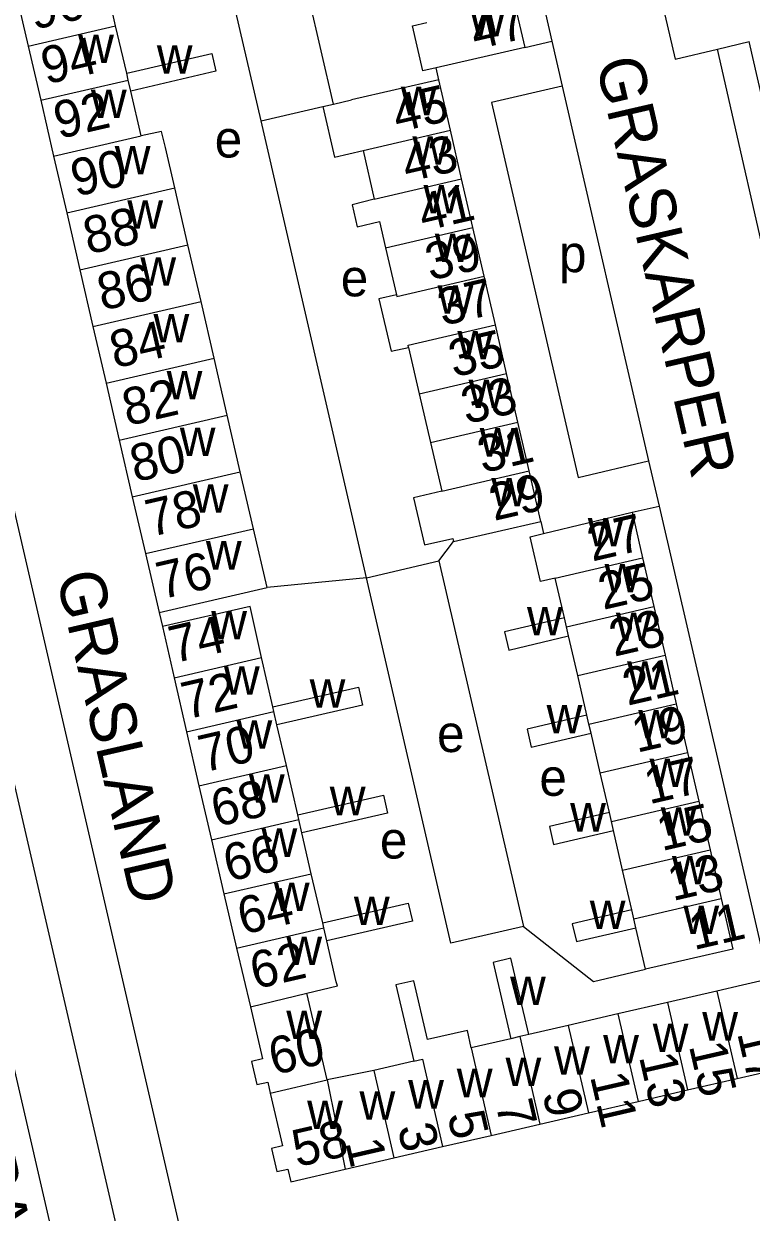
# Model space of a CAD drawing. Extents: x 155696 to 157795, y 382328 to 384028.
# Drawn here: x 156930.4 to 157009.1, y 383217.2 to 383345.7 of the extents above; entities that cross this region are included whole.
import ezdxf

# ---------------------------------------------------------------- set-up
doc = ezdxf.new("R2010")
doc.units = 0
for name, color, linetype in [('BLT_Basislijn', 7, 'Continuous'), ('BLT_Bebouwing', 7, 'Continuous'), ('BLT_Centroide', 7, 'Continuous'), ('BLT_Huisnummer', 7, 'Continuous'), ('BLT_Huisnummer_ tussenligend', 7, 'Continuous'), ('BLT_Onderverdeling_panden', 7, 'Continuous'), ('BLT_Straatnaam', 7, 'Continuous')]:
    doc.layers.add(name, color=color, linetype=linetype)

msp = doc.modelspace()

# ---------------------------------------------------------------- linework, layer by layer
at = {"layer": 'BLT_Basislijn'}
for p, q in [((156976.32, 383392.48), (156987.55, 383343.86)), ((156963.94, 383337.05), (156952.41, 383386.99)), ((156956.1, 383335.24), (156944.56, 383385.17)), ((156999.79, 383346.69), (157000.9, 383341.9)), ((156984.62, 383343.18), (156987.55, 383343.86)), ((156987.55, 383343.86), (156988.67, 383338.99)), ((157005.47, 383342.98), (157008.92, 383343.8)), ((157018.13, 383303.23), (157008.92, 383343.8)), ((157000.9, 383341.9), (157005.47, 383342.98)), ((157014.68, 383302.42), (157005.47, 383342.98)), ((156975.33, 383339.68), (156975.03, 383340.97)), ((156988.67, 383338.99), (156981.02, 383337.22)), ((156988.67, 383338.99), (156998.03, 383298.47)), ((156956.1, 383335.24), (156962.8, 383336.79)), ((156981.02, 383337.22), (156990.4, 383296.67)), ((156967.51, 383285.84), (156956.1, 383335.24)), ((156990.4, 383296.67), (156998.03, 383298.47)), ((156998.03, 383298.47), (156999.16, 383293.59)), ((156996.24, 383292.91), (156999.16, 383293.59)), ((156999.16, 383293.59), (157010.98, 383242.43)), ((156986.36, 383291.93), (156986.67, 383290.61)), ((156975.35, 383287.65), (156976.91, 383289.74)), ((156967.51, 383285.84), (156975.35, 383287.65)), ((156975.35, 383287.65), (156984.48, 383248.13)), ((156967.51, 383285.84), (156956.76, 383284.78)), ((156976.63, 383246.32), (156967.51, 383285.84)), ((156945.07, 383282.06), (156945.44, 383280.56)), ((156984.48, 383248.13), (156976.63, 383246.32))]:
    msp.add_line(p, q, dxfattribs=at)
for points in [[(156983.21, 383030.72), (156967.38, 383099.24), (156870.41, 383519.08), (156869.37, 383522.79), (156868.15, 383526.38), (156866.54, 383529.72), (156865.07, 383532.4), (156812.59, 383620.85)], [(156899.98, 383420.38), (156963.72, 383144.42)], [(156906.38, 383332.24), (156973.29, 383042.58), (156975.17, 383034.43)], [(156984.48, 383248.13), (156992.05, 383242.19), (156997.69, 383243.5)]]:
    msp.add_lwpolyline(points, dxfattribs=at)
at = {"layer": 'BLT_Bebouwing'}
for p, q in [((156940.37, 383345.49), (156939.32, 383350.13)), ((156929.57, 383349.15), (156930.92, 383343.31)), ((156983.5, 383348.06), (156984.62, 383343.18)), ((156972.48, 383345.51), (156974.05, 383345.87)), ((156941.57, 383340.39), (156940.37, 383345.49)), ((156973.6, 383340.64), (156972.48, 383345.51)), ((156930.92, 383343.31), (156932.27, 383337.46)), ((156984.62, 383343.18), (156975.03, 383340.97)), ((156975.03, 383340.97), (156973.6, 383340.64)), ((156975.33, 383339.68), (156965.87, 383337.49)), ((156976.59, 383334.22), (156975.33, 383339.68)), ((156943.12, 383333.6), (156942.02, 383338.45)), ((156932.27, 383337.46), (156933.67, 383331.41)), ((156962.8, 383336.79), (156963.94, 383337.05)), ((156963.94, 383337.05), (156965.87, 383337.49)), ((156977.8, 383328.96), (156976.59, 383334.22)), ((156946.78, 383327.98), (156945.77, 383332.35)), ((156967.14, 383332.03), (156968.35, 383326.77)), ((156933.67, 383331.41), (156935.08, 383325.28)), ((156948.19, 383321.84), (156946.78, 383327.98)), ((156979.02, 383323.69), (156977.8, 383328.96)), ((156935.08, 383325.28), (156936.5, 383319.14)), ((156980.23, 383318.43), (156979.02, 383323.69)), ((156949.61, 383315.7), (156948.19, 383321.84)), ((156969.57, 383321.51), (156970.74, 383316.42)), ((156936.5, 383319.14), (156937.92, 383313)), ((156981.45, 383313.17), (156980.23, 383318.43)), ((156951.03, 383309.56), (156949.61, 383315.7)), ((156937.92, 383313), (156939.34, 383306.86)), ((156982.67, 383307.91), (156981.45, 383313.17)), ((156972.06, 383310.73), (156973.21, 383305.73)), ((156952.44, 383303.42), (156951.03, 383309.56)), ((156983.88, 383302.65), (156982.67, 383307.91)), ((156939.34, 383306.86), (156940.75, 383300.72)), ((156973.21, 383305.73), (156974.43, 383300.47)), ((156953.86, 383297.28), (156952.44, 383303.42)), ((156985.1, 383297.39), (156983.88, 383302.65)), ((156940.75, 383300.72), (156942.17, 383294.58)), ((156974.43, 383300.47), (156975.65, 383295.2)), ((156955.28, 383291.14), (156953.86, 383297.28)), ((156986.36, 383291.93), (156985.1, 383297.39)), ((156942.17, 383294.58), (156943.59, 383288.44)), ((156976.91, 383289.74), (156986.36, 383291.93)), ((156986.67, 383290.61), (156996.24, 383292.91)), ((156996.24, 383292.91), (156997.38, 383287.98)), ((156956.76, 383284.78), (156955.28, 383291.14)), ((156985.23, 383290.27), (156986.67, 383290.61)), ((156986.34, 383285.42), (156985.23, 383290.27)), ((156943.59, 383288.44), (156945.07, 383282.06)), ((156997.38, 383287.98), (156998.59, 383282.71)), ((156987.93, 383285.79), (156986.34, 383285.42)), ((156988.92, 383281.49), (156987.93, 383285.79)), ((156945.07, 383282.06), (156956.76, 383284.78)), ((156954.92, 383282.74), (156945.44, 383280.56)), ((156956.14, 383277.22), (156954.92, 383282.74)), ((156998.59, 383282.71), (156999.81, 383277.45)), ((156945.44, 383280.56), (156946.69, 383275.03)), ((156990.36, 383275.27), (156989.37, 383279.54)), ((156957.38, 383271.87), (156956.14, 383277.22)), ((156999.81, 383277.45), (157001.02, 383272.19)), ((156991.35, 383270.97), (156990.36, 383275.27)), ((156946.69, 383275.03), (156948.04, 383269.19)), ((157001.02, 383272.19), (157002.24, 383266.93)), ((156958.84, 383265.52), (156957.82, 383269.93)), ((156948.04, 383269.19), (156949.39, 383263.34)), ((156992.79, 383264.74), (156991.8, 383269.02)), ((157002.24, 383266.93), (157003.45, 383261.67)), ((156960.07, 383260.19), (156958.84, 383265.52)), ((156993.78, 383260.46), (156992.79, 383264.74)), ((156949.39, 383263.34), (156950.74, 383257.49)), ((157003.45, 383261.67), (157004.67, 383256.41)), ((156995.22, 383254.22), (156994.23, 383258.51)), ((156950.74, 383257.49), (156952.09, 383251.65)), ((156961.54, 383253.83), (156960.52, 383258.26)), ((157004.67, 383256.41), (157005.88, 383251.14)), ((156962.77, 383248.52), (156961.54, 383253.83)), ((156996.21, 383249.94), (156995.22, 383254.22)), ((156952.09, 383251.65), (156953.44, 383245.8)), ((157005.88, 383251.14), (157007.15, 383245.68)), ((156997.69, 383243.5), (156996.66, 383247.99)), ((156953.44, 383245.8), (156954.95, 383239.43)), ((156964.24, 383242.14), (156963.22, 383246.59)), ((157007.15, 383245.68), (156997.69, 383243.5)), ((156961.07, 383240.92), (156964.36, 383241.72)), ((156964.36, 383241.72), (156964.24, 383242.14)), ((157008.2, 383241.79), (157005.42, 383241.15)), ((157010.98, 383242.43), (157008.2, 383241.79)), ((156963.25, 383231.55), (156961.07, 383240.92)), ((157005.42, 383241.15), (157000.06, 383239.91)), ((157000.06, 383239.91), (156994.7, 383238.67)), ((156994.7, 383238.67), (156989.34, 383237.43)), ((156989.34, 383237.43), (156985.07, 383236.45)), ((156983.13, 383236), (156978.82, 383235)), ((156972.62, 383233.57), (156968.29, 383232.57)), ((157007.6, 383231.7), (157013.26, 383233)), ((156968.29, 383232.57), (156963.25, 383231.55)), ((157002.24, 383230.46), (157007.6, 383231.7)), ((156996.88, 383229.22), (157002.24, 383230.46)), ((156991.52, 383227.98), (156996.88, 383229.22)), ((156986.26, 383226.77), (156991.52, 383227.98)), ((156981, 383225.55), (156986.26, 383226.77)), ((156975.74, 383224.34), (156981, 383225.55)), ((156970.48, 383223.12), (156975.74, 383224.34)), ((156965.22, 383221.91), (156970.48, 383223.12)), ((156959.32, 383220.53), (156965.22, 383221.91))]:
    msp.add_line(p, q, dxfattribs=at)
for points in [[(156941.57, 383340.39), (156950.79, 383342.53), (156951.23, 383340.59), (156942.02, 383338.45)], [(156962.8, 383336.79), (156964.05, 383331.3), (156967.14, 383332.03)], [(156945.77, 383332.35), (156945.35, 383334.09), (156943.12, 383333.6)], [(156968.35, 383326.77), (156965.96, 383326.17), (156966.51, 383323.79), (156968.91, 383324.35), (156969.57, 383321.51)], [(156970.74, 383316.42), (156968.86, 383315.98), (156970.18, 383310.32), (156972.06, 383310.73)], [(156975.65, 383295.2), (156972.61, 383294.47), (156973.79, 383289.38), (156976.85, 383290.09), (156976.91, 383289.74)], [(156988.92, 383281.49), (156982.44, 383279.98), (156982.9, 383278.02), (156989.37, 383279.54)], [(156957.38, 383271.87), (156966.63, 383274.01), (156967.08, 383272.06), (156957.82, 383269.93)], [(156991.35, 383270.97), (156984.88, 383269.45), (156985.32, 383267.51), (156991.8, 383269.02)], [(156960.07, 383260.19), (156969.34, 383262.32), (156969.79, 383260.39), (156960.52, 383258.26)], [(156993.78, 383260.46), (156987.31, 383258.95), (156987.75, 383256.99), (156994.23, 383258.51)], [(156962.77, 383248.52), (156972.02, 383250.65), (156972.47, 383248.72), (156963.22, 383246.59)], [(156996.21, 383249.94), (156989.75, 383248.43), (156990.21, 383246.49), (156996.66, 383247.99)], [(156985.07, 383236.45), (156983.14, 383244.7), (156981.21, 383244.25), (156983.13, 383236)], [(156978.82, 383235), (156978.42, 383236.89), (156974.12, 383235.91), (156972.64, 383242.27), (156970.7, 383241.82), (156972.62, 383233.57)], [(156954.95, 383239.43), (156956.25, 383233.82), (156955.07, 383233.55), (156955.65, 383231.04), (156956.83, 383231.29), (156957.1, 383230.12)], [(156957.1, 383230.12), (156958.42, 383224.41), (156957.24, 383224.13), (156957.82, 383221.64), (156959.01, 383221.89), (156959.32, 383220.53)]]:
    msp.add_lwpolyline(points, dxfattribs=at)
at = {"layer": 'BLT_Onderverdeling_panden'}
for p, q in [((156930.92, 383343.31), (156940.37, 383345.49)), ((156932.27, 383337.46), (156941.72, 383339.64)), ((156941.72, 383339.64), (156941.57, 383340.39)), ((156942.02, 383338.45), (156941.72, 383339.64)), ((156967.14, 383332.03), (156976.59, 383334.22)), ((156933.67, 383331.41), (156943.12, 383333.6)), ((156935.08, 383325.28), (156946.78, 383327.98)), ((156968.35, 383326.77), (156977.8, 383328.96)), ((156969.57, 383321.51), (156979.02, 383323.69)), ((156936.5, 383319.14), (156948.19, 383321.84)), ((156937.92, 383313), (156949.61, 383315.7)), ((156939.34, 383306.86), (156951.03, 383309.56)), ((156973.21, 383305.73), (156982.67, 383307.91)), ((156940.75, 383300.72), (156952.44, 383303.42)), ((156974.43, 383300.47), (156983.88, 383302.65)), ((156942.17, 383294.58), (156953.86, 383297.28)), ((156975.65, 383295.2), (156985.1, 383297.39)), ((156943.59, 383288.44), (156955.28, 383291.14)), ((156987.93, 383285.79), (156997.38, 383287.98)), ((156989.14, 383280.53), (156988.92, 383281.49)), ((156989.14, 383280.53), (156998.59, 383282.71)), ((156989.37, 383279.54), (156989.14, 383280.53)), ((156946.69, 383275.03), (156956.14, 383277.22)), ((156990.36, 383275.27), (156999.81, 383277.45)), ((156948.04, 383269.19), (156957.49, 383271.37)), ((156957.49, 383271.37), (156957.38, 383271.87)), ((156957.82, 383269.93), (156957.49, 383271.37)), ((156991.57, 383270.01), (157001.02, 383272.19)), ((156991.57, 383270.01), (156991.35, 383270.97)), ((156991.8, 383269.02), (156991.57, 383270.01)), ((156992.79, 383264.74), (157002.24, 383266.93)), ((156949.39, 383263.34), (156958.84, 383265.52)), ((156994, 383259.48), (157003.45, 383261.67)), ((156950.74, 383257.49), (156960.19, 383259.68)), ((156960.19, 383259.68), (156960.07, 383260.19)), ((156960.52, 383258.26), (156960.19, 383259.68)), ((156994, 383259.48), (156993.78, 383260.46)), ((156994.23, 383258.51), (156994, 383259.48)), ((156995.22, 383254.22), (157004.67, 383256.41)), ((156952.09, 383251.65), (156961.54, 383253.83)), ((156996.43, 383248.96), (157005.88, 383251.14)), ((156996.43, 383248.96), (156996.21, 383249.94)), ((156962.89, 383247.99), (156962.77, 383248.52)), ((156996.66, 383247.99), (156996.43, 383248.96)), ((156953.44, 383245.8), (156962.89, 383247.99)), ((156963.22, 383246.59), (156962.89, 383247.99)), ((156954.95, 383239.43), (156961.07, 383240.92)), ((157005.42, 383241.15), (157007.6, 383231.7)), ((157000.06, 383239.91), (157002.24, 383230.46)), ((156994.7, 383238.67), (156996.88, 383229.22)), ((156989.34, 383237.43), (156991.52, 383227.98)), ((156984.08, 383236.22), (156983.13, 383236)), ((156985.07, 383236.45), (156984.08, 383236.22)), ((156984.08, 383236.22), (156986.26, 383226.77)), ((156978.82, 383235), (156981, 383225.55)), ((156957.1, 383230.12), (156963.25, 383231.55)), ((156963.25, 383231.55), (156965.22, 383221.91)), ((156968.29, 383232.57), (156970.48, 383223.12))]:
    msp.add_line(p, q, dxfattribs=at)
for points in [[(156970.74, 383316.42), (156970.78, 383316.25), (156980.23, 383318.43)], [(156972.06, 383310.73), (156972, 383310.99), (156981.45, 383313.17)], [(156972.62, 383233.57), (156973.56, 383233.79), (156975.74, 383224.34)]]:
    msp.add_lwpolyline(points, dxfattribs=at)

# ---------------------------------------------------------------- texts
at = {"layer": 'BLT_Centroide'}
for s, p in [('w', (156978.7, 383344.38)), ('w', (156936.32, 383341.47)), ('w', (156944.83, 383340.34)), ('w', (156937.7, 383335.53)), ('w', (156971.23, 383335.84)), ('e', (156951.09, 383331.27)), ('w', (156972.47, 383330.5)), ('w', (156940.28, 383329.44)), ('w', (156973.68, 383325.22)), ('w', (156941.64, 383323.56)), ('w', (156974.9, 383319.97)), ('p', (156988.34, 383318.87)), ('w', (156943.05, 383317.41)), ('e', (156964.73, 383316.26)), ('w', (156975.2, 383314.38)), ('w', (156944.47, 383311.28)), ('w', (156977.34, 383309.44)), ('w', (156945.89, 383305.12)), ('w', (156978.55, 383304.19)), ('w', (156947.31, 383299)), ('w', (156979.76, 383298.94)), ('w', (156948.72, 383292.88)), ('w', (156981.01, 383293.56)), ('w', (156991.45, 383289.22)), ('w', (156950.14, 383286.72)), ('w', (156993.26, 383284.25)), ('w', (156950.72, 383279.16)), ('w', (156984.87, 383279.61)), ('w', (156994.48, 383279)), ('w', (156995.7, 383273.72)), ('w', (156952.09, 383273.19)), ('w', (156961.36, 383271.79)), ('w', (156986.99, 383269.01)), ('w', (156996.9, 383268.47)), ('w', (156953.45, 383267.34)), ('e', (156975.14, 383266.99)), ('w', (156998.12, 383263.22)), ('e', (156986.21, 383262.26)), ('w', (156954.79, 383261.5)), ('w', (156963.54, 383260.16)), ('w', (156989.54, 383258.4)), ('w', (156999.34, 383257.94)), ('w', (156956.15, 383255.66)), ('e', (156968.96, 383255.48)), ('w', (157000.55, 383252.69)), ('w', (156957.49, 383249.81)), ('w', (156966.15, 383248.28)), ('w', (156991.66, 383247.86)), ('w', (157001.79, 383247.31)), ('w', (156958.84, 383243.97)), ('w', (156983.04, 383239.65)), ('w', (156958.84, 383235.95)), ('w', (157003.83, 383235.8)), ('w', (156998.47, 383234.56)), ('w', (156993.11, 383233.33)), ('w', (156982.55, 383230.89)), ('w', (156987.8, 383232.11)), ('w', (156977.28, 383229.67)), ('w', (156972.02, 383228.45)), ('w', (156966.75, 383227.23)), ('w', (156961.09, 383226.23))]:
    msp.add_text(s, height=4, dxfattribs=at).set_placement(p)
at = {"layer": 'BLT_Huisnummer'}
for s, rotation, p in [('47', 13.0061, (156979.28, 383342.91)), ('94', 12.986, (156932.85, 383339.16)), ('92', 12.986, (156934.22, 383333.26)), ('45', 13.0061, (156970.86, 383333.97)), ('41', 13.0061, (156973.66, 383323.28)), ('88', 12.986, (156937.41, 383320.78)), ('37', 13.0061, (156975.74, 383313.05)), ('84', 12.986, (156940.27, 383308.46)), ('33', 13.0061, (156978.28, 383302.43)), ('80', 12.986, (156942.46, 383296.15)), ('29', 13.0061, (156981.3, 383291.97)), ('27', 13.0061, (156991.92, 383287.58)), ('76', 12.986, (156945.32, 383283.49)), ('74', 12.986, (156946.67, 383276.58)), ('23', 13.0061, (156994.29, 383277.29)), ('19', 13.0061, (156996.75, 383266.9)), ('70', 12.986, (156949.87, 383264.77)), ('15', 13.0061, (156999.45, 383256.27)), ('66', 12.986, (156952.57, 383252.96)), ('11', 13.0061, (157002.92, 383245.57)), ('62', 12.986, (156955.45, 383241.33)), ('17', 283.0035, (157007.59, 383236.61)), ('13', 283.0035, (156996.97, 383234.06)), ('7', 283.0035, (156981.46, 383228.95)), ('58', 12.986, (156959.99, 383222.1)), ('1', 283.0035, (156965.21, 383224.79))]:
    msp.add_text(s, height=4, rotation=rotation, dxfattribs=at).set_placement(p)
at = {"layer": 'BLT_Huisnummer_ tussenligend'}
for s, rotation, p in [('96', 12.986, (156931.51, 383345.06)), ('43', 13.0061, (156971.88, 383328.58)), ('90', 12.986, (156936.06, 383327.02)), ('39', 13.0061, (156974.4, 383317.95)), ('86', 12.986, (156938.92, 383314.7)), ('35', 13.0061, (156976.93, 383307.49)), ('82', 12.986, (156941.63, 383302.22)), ('31', 13.0061, (156980.06, 383297.13)), ('78', 12.986, (156944.15, 383290.24)), ('25', 13.0061, (156993.11, 383282.35)), ('21', 13.0061, (156995.74, 383271.99)), ('72', 12.986, (156948.03, 383270.51)), ('17', 13.0061, (156998.09, 383261.33)), ('68', 12.986, (156951.23, 383258.87)), ('13', 13.0061, (157000.63, 383250.87)), ('64', 12.986, (156954.09, 383247.23)), ('60', 12.986, (156957.46, 383232.05)), ('15', 283.0035, (157002.37, 383235.24)), ('11', 283.0035, (156991.68, 383231.94)), ('9', 283.0035, (156986.52, 383230.12)), ('5', 283.0035, (156976.24, 383227.76)), ('3', 283.0035, (156970.85, 383226.41))]:
    msp.add_text(s, height=4, rotation=rotation, dxfattribs=at).set_placement(p)
at = {"layer": 'BLT_Straatnaam'}
for s, rotation, p in [('GRASKARPER', 283.0059, (156992.3, 383341.59)), ('GRASLAND', 283.0061, (156933.93, 383286.04)), ('GRASPIEPER', 283.0061, (156923.15, 383228.62))]:
    msp.add_text(s, height=5, rotation=rotation, dxfattribs=at).set_placement(p)

doc.saveas('drawing.dxf')
